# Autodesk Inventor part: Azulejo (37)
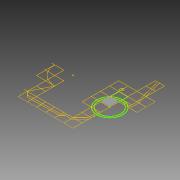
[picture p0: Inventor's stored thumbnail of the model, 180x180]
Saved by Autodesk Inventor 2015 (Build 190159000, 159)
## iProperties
Created: 2015-04
Part Number: Azulejo (37)
Material: Genérico
Document SubType Name: Modeling
Designer: Felipe
Density: 1 g/cm^3
Appearance: Padrão
Author: Felipe
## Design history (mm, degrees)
sketch "Sketch1"
  geometry: L1 (-1510, -7490)-(-1510, -6010); L2 (-3010, -1490)-(-3010, -10); L3 (-2990, 10)-(-1510, 10); L4 (-1510, -10)-(-2990, -10); L5 (-1510, -1490)-(-1510, -10); L6 (-1490, -10)-(-1490, -1490); L7 (-1490, -1490)-(-10, -1490); L8 (-10, -1510)-(-1490, -1510); L9 (-10, -2990)-(-10, -1510); L10 (-10, -5990)-(-10, -4510); L11 (-1490, -7490)-(-10, -7490); L12 (4490, -6010)-(3010, -6010); L13 (10, -1510)-(10, -2990); L14 (10, -3010)-(10, -4490); L15 (10, -4510)-(10, -5990); L16 (10, -5990)-(1490, -5990); L17 (1490, -6010)-(10, -6010); L18 (10, -7490)-(1490, -7490); L19 (1510, -5990)-(2990, -5990); L20 (2990, -6010)-(1510, -6010); L21 (1510, -7490)-(2990, -7490); L22 (4490, 1510)-(4490, 2990); L23 (4490, 10)-(4490, 1490); L24 (4490, -1490)-(4490, -10); L25 (4490, -2990)-(4490, -1510); L26 (3010, -5990)-(4490, -5990); L27 (3010, -7490)-(4490, -7490); L28 (4510, 3010)-(5990, 3010); L29 (5990, 2990)-(4510, 2990); L30 (4510, 2990)-(4510, 1510); L31 (4510, 1510)-(5990, 1510); L32 (5990, 1510)-(5990, 1740.185); L33 (5990, 1760.2)-(5990, 2259.8); L34 (5990, 2279.815)-(5990, 2990); L35 (5990, 1490)-(4510, 1490); L36 (4510, 1490)-(4510, 10); L37 (4510, 10)-(5990, 10); L38 (5990, 10)-(5990, 1490); L39 (5975.983, -10)-(4510, -10); L40 (4510, -10)-(4510, -1490); L41 (5990, -1510)-(5782.897, -1510); L42 (5782.897, -1510)-(5688.66, -1510); L43 (5668.66, -1510)-(5482.895, -1510); L44 (5482.895, -1510)-(5388.656, -1510); L45 (5368.656, -1510)-(4510, -1510); L46 (4510, -1510)-(4510, -2990); L47 (4510, -2990)-(5975.983, -2990); L48 (5990, -2975.728)-(5990, -2837.377); L49 (5990, -2837.377)-(5990, -2536.247); L50 (5990, -2500.476)-(5990, -2317.632); L51 (5990, -2317.632)-(5990, -1510); L52 (5990, -3010)-(4510, -3010); L53 (5990, -4490)-(5990, -3010); L54 (4510, -5990)-(5990, -5990); L55 (5990, -5990)-(5990, -4510); L56 (4510, -7490)-(5990, -7490); L57 (5990, -7490)-(5990, -6310); L58 (5990, -6290)-(5990, -6010); L59 (7490, 4510)-(7490, 5990); L60 (6010, 3010)-(7490, 3010); L61 (7490, 3010)-(7490, 4490); L62 (7490, 2990)-(6010, 2990); L63 (6010, 2990)-(6010, 2279.815); L64 (6010, 2259.8)-(6010, 1760.2)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; A1 r 250 centre (6000, 2010) between (5990, 2259.8) and (5990, 1760.2); A2 r 250 centre (6000, 2010) between (6010, 1760.2) and (6010, 2259.8); A3 r 270 centre (6000, 2010) between (5990, 2279.815) and (5990, 1740.185); A4 r 270 centre (6000, 2010) between (6010, 1740.185) and (6010, 2279.815); A5 r 3010.017 centre (0, 0) between (-1490, -2615.358) and (-346.554, -2990); A6 r 2990.017 centre (0, 0) between (-1490, -2592.316) and (-10, -2990); A7 r 3010.017 centre (0, 0) between (-2603.863, -1510) and (-1510, -2603.863); A8 r 2990.017 centre (0, 0) between (-2580.717, -1510) and (-1510, -2580.717); A9 r 3010.017 centre (0, 0) between (-2990, -346.554) and (-2615.358, -1490); A10 r 2990.017 centre (0, 0) between (-2990, -10) and (-2592.316, -1490); A11 r 2131.367 centre (7500, -1500) between (7490, 631.344) and (6010, 24.017); A12 r 2131.367 centre (7500, -1500) between (5975.983, -10) and (5368.656, -1490); A13 r 2131.367 centre (7500, -1500) between (5368.656, -1510) and (5975.983, -2990); A14 r 2131.367 centre (7500, -1500) between (6010, -3024.017) and (7190, -3608.703); A15 r 1831.367 centre (7500, -1500) between (7490.321, 331.342) and (6463.753, 10); A16 r 1831.367 centre (7500, -1500) between (7489.976, 331.34) and (6010, -435.196); A17 r 1831.367 centre (7500, -1500) between (5990, -463.753) and (5668.66, -1490); A18 r 1831.367 centre (7500, -1500) between (5668.66, -1510) and (5990, -2536.247); A19 r 1831.367 centre (7500, -1500) between (6010, -2564.804) and (6435.196, -2990); A20 r 1831.367 centre (7500, -1500) between (6463.753, -3010) and (7490, -3331.34); A21 r 2111.367 centre (7500, -1500) between (7490.389, 611.346) and (6024.272, 10); A22 r 2111.367 centre (7500, -1500) between (5990, -24.272) and (5388.656, -1490); A23 r 2111.367 centre (7500, -1500) between (5388.656, -1510) and (5990, -2975.728); A24 r 2111.367 centre (7500, -1500) between (6024.272, -3010) and (7210, -3591.357); A25 r 1811.367 centre (7499.986, -1499.91) between (7490.524, 311.432) and (6499.51, 10.09); A26 r 1811.367 centre (7500, -1500) between (6469.975, -10) and (6010, -469.975); A27 r 1811.367 centre (7500, -1500) between (5990, -499.524) and (5688.66, -1490); A28 r 1811.367 centre (7500, -1500) between (5688.66, -1510) and (5990, -2500.476); A29 r 1811.367 centre (7500, -1500) between (6010, -2530.025) and (6469.975, -2990); A30 r 1811.367 centre (7500, -1500) between (6499.524, -3010) and (7490, -3311.34); A31 r 449.871 centre (7499.449, -4060.672) between (7510, -4510.419) and (7521.546, -4510); A32 r 2111.367 centre (7500, -1500) between (7490.019, 611.344) and (7490.389, 611.346); A33 r 1831.367 centre (7500, -1500) between (7489.976, 331.34) and (7490.321, 331.342); A34 r 1811.367 centre (7499.986, -1499.91) between (7489.986, 311.429) and (7490.524, 311.432); 12 further points
  constraints: 714 end point, 75 point on circle, 34 centre point, 13 point on line, 3 concentric, 2 parallel, 2 perpendicular, 1 collinear, 1 horizontal, 1 vertical, 6 other
extrude "Extrusion1" new body sketch "Sketch1" distance "d0" = 60; taper "d1" = 0 deg
extrude "Extrusion2" new body sketch "Sketch1" distance "d2" = 60; taper "d3" = 0 deg
body "Solid1"
body "Solid2"
